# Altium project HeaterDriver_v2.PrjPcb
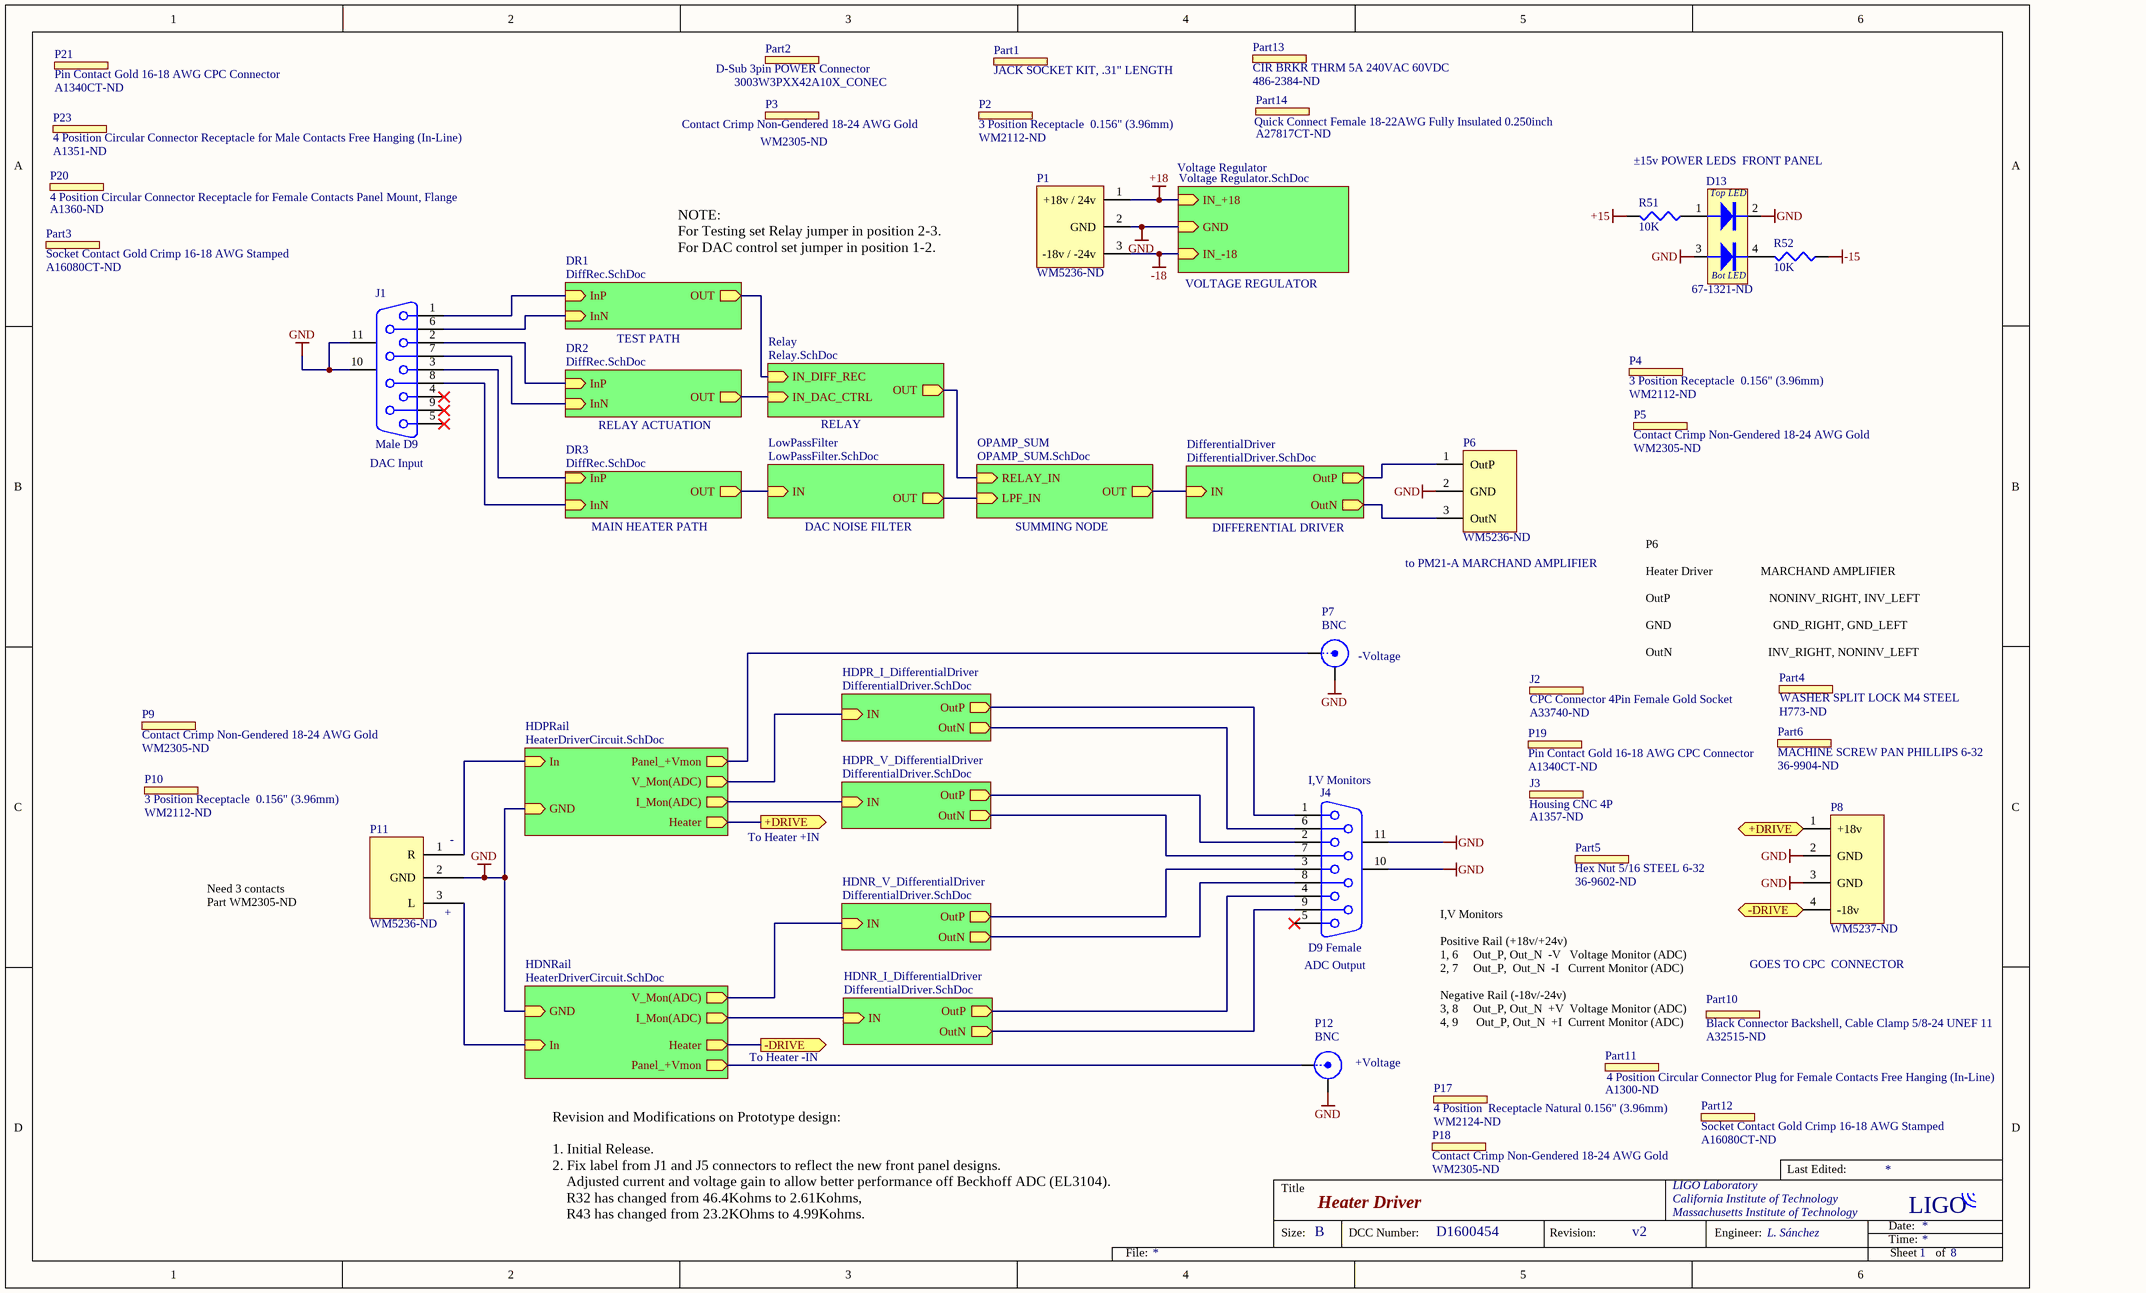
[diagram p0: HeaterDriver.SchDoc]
8 sheets, 310 parts. Net scope: hierarchical (ports join the sheet entries above them; power ports are global).
Board file: HeaterContollerDriver_v2.PcbDoc
Sheets:
  HeaterDriver.SchDoc
    Relay = Relay.SchDoc
    OPAMP_SUM = OPAMP_SUM.SchDoc
    LowPassFilter = LowPassFilter.SchDoc
    DR1 = DiffRec.SchDoc
    DR2 = DiffRec.SchDoc
    DR3 = DiffRec.SchDoc
    HDPR_I_DifferentialDriver = DifferentialDriver.SchDoc
    HDPR_V_DifferentialDriver = DifferentialDriver.SchDoc
    HDNR_I_DifferentialDriver = DifferentialDriver.SchDoc
    HDNR_V_DifferentialDriver = DifferentialDriver.SchDoc
    Voltage Regulator = Voltage Regulator.SchDoc
    HDPRail = HeaterDriverCircuit.SchDoc
    HDNRail = HeaterDriverCircuit.SchDoc
    DifferentialDriver = DifferentialDriver.SchDoc

## Sheet HeaterDriver.SchDoc: Heater Driver
size B; Organization: LIGO Laboratory; Address1: California Institute of Technology; Address2: Massachusetts Institute of Technology; DocumentNumber: D1600454; Revision: v2; SheetNumber: 1; SheetTotal: 8; Engineer: L. Sánchez

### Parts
D13  Digikey Part Number: 67-1321-ND  [my LUMEX Dual LED]  (hidden comment: Stacked LED)
J1  Male D9  [MY_DB9M_RA]
J2  CPC Connector 4Pin Female Gold Socket  Digikey Part Number: A33740-ND  (mechanical)
J3  Housing CNC 4P  Digikey Part Number: A1357-ND  (mechanical)
J4  D9 Female  [MY_DB9F_RA]
P1  Digikey Part Number: WM5236-ND  [MOLEX_156_3P_RA_PS_IN]  (hidden comment: Molex 3p 0.156inch RA)
P2  3 Position Receptacle  0.156" (3.96mm)  Digikey Part Number: WM2112-ND  (mechanical)
P3  Contact Crimp Non-Gendered 18-24 AWG Gold  Digikey Part Number: WM2305-ND  (mechanical)
P4  3 Position Receptacle  0.156" (3.96mm)  Digikey Part Number: WM2112-ND  (mechanical)
P5  Contact Crimp Non-Gendered 18-24 AWG Gold  Digikey Part Number: WM2305-ND  (mechanical)
P6  Digikey Part Number: WM5236-ND  [Header 0.156 3p PM21-A]  (hidden comment: Molex 3p 0.156inch RA)
P7  BNC  [BNC Straight Away Connector]
P8  Digikey Part Number: WM5237-ND  [HEADER  4p 0.156inch]  (hidden comment: Molex Header 4p 0.156inch RA)
P9  Contact Crimp Non-Gendered 18-24 AWG Gold  Digikey Part Number: WM2305-ND  (mechanical)
P10  3 Position Receptacle  0.156" (3.96mm)  Digikey Part Number: WM2112-ND  (mechanical)
P11  Digikey Part Number: WM5236-ND  [MOLEX_156_RA_3_+2Driver]  (hidden comment: Molex 3p 0.156inch RA)
P12  BNC  [BNC Straight Away Connector]
P17  4 Position  Receptacle Natural 0.156" (3.96mm)  Digikey Part Number: WM2124-ND  (mechanical)
P18  Contact Crimp Non-Gendered 18-24 AWG Gold  Digikey Part Number: WM2305-ND  (mechanical)
P19  Pin Contact Gold 16-18 AWG CPC Connector  Digikey Part Number: A1340CT-ND  (mechanical)
P20  4 Position Circular Connector Receptacle for Female Contacts Panel Mount, Flange  Digikey Part Number: A1360-ND  (mechanical)
P21  Pin Contact Gold 16-18 AWG CPC Connector  Digikey Part Number: A1340CT-ND  (mechanical)
P23  4 Position Circular Connector Receptacle for Male Contacts Free Hanging (In-Line)  Digikey Part Number: A1351-ND  (mechanical)
Part1  JACK SOCKET KIT, .31" LENGTH  (mechanical)
Part2  D-Sub 3pin POWER Connector  CONEC: 3003W3PXX42A10X_CONEC  (mechanical)
Part3  Socket Contact Gold Crimp 16-18 AWG Stamped  Digikey Part Number: A16080CT-ND  (mechanical)
Part4  WASHER SPLIT LOCK M4 STEEL  Digikey Part Number: H773-ND  (mechanical)
Part5  Hex Nut 5/16 STEEL 6-32  Digikey Part Number: 36-9602-ND  (mechanical)
Part6  MACHINE SCREW PAN PHILLIPS 6-32  Digikey Part Number: 36-9904-ND  (mechanical)
Part10  Black Connector Backshell, Cable Clamp 5/8-24 UNEF 11  Digikey Part Number: A32515-ND  (mechanical)
Part11  4 Position Circular Connector Plug for Female Contacts Free Hanging (In-Line)  Digikey Part Number: A1300-ND  (mechanical)
Part12  Socket Contact Gold Crimp 16-18 AWG Stamped  Digikey Part Number: A16080CT-ND  (mechanical)
Part13  CIR BRKR THRM 5A 240VAC 60VDC  Digikey Part Number: 486-2384-ND  (mechanical)
Part14  Quick Connect Female 18-22AWG Fully Insulated 0.250inch  Digikey Part Number: A27817CT-ND  (mechanical)
R51  value 10K  [1206]  (hidden comment: SMD Res 1206 10K 1% 0.25W)
R52  value 10K  [1206]  (hidden comment: SMD Res 1206 10K 1% 0.25W)

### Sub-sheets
DifferentialDriver = DifferentialDriver.SchDoc: IN (in), OutN (out), OutP (out)
DR1 = DiffRec.SchDoc: InP (in), InN (in), OUT (out)
DR2 = DiffRec.SchDoc: InP (in), InN (in), OUT (out)
DR3 = DiffRec.SchDoc: InP (in), InN (in), OUT (out)
HDNR_I_DifferentialDriver = DifferentialDriver.SchDoc: IN (in), OutN (out), OutP (out)
HDNR_V_DifferentialDriver = DifferentialDriver.SchDoc: IN (in), OutN (out), OutP (out)
HDNRail = HeaterDriverCircuit.SchDoc: In (in), GND (in), I_Mon(ADC) (out), Heater (out), Panel_+Vmon (out), V_Mon(ADC) (out)
HDPR_I_DifferentialDriver = DifferentialDriver.SchDoc: IN (in), OutN (out), OutP (out)
HDPR_V_DifferentialDriver = DifferentialDriver.SchDoc: IN (in), OutN (out), OutP (out)
HDPRail = HeaterDriverCircuit.SchDoc: In (in), GND (in), I_Mon(ADC) (out), Heater (out), Panel_+Vmon (out), V_Mon(ADC) (out)
LowPassFilter = LowPassFilter.SchDoc: IN (in), OUT (out)
OPAMP_SUM = OPAMP_SUM.SchDoc: RELAY_IN (in), LPF_IN (in), OUT (out)
Relay = Relay.SchDoc: IN_DAC_CTRL (in), IN_DIFF_REC (in), OUT (out)
Voltage Regulator = Voltage Regulator.SchDoc: IN_+18 (in), GND (in), IN_-18 (in)

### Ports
+DRIVE (out), -DRIVE (out)

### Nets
+15: R51.2
+18: P1.1(+18v_/_24v) ; sheet Voltage Regulator/IN_+18
-15: R52.1
-18: P1.3(-18v_/_-24v) ; sheet Voltage Regulator/IN_-18
GND: D13.2(CATHODE) D13.3(ANODE) J1.10(MH1) J1.11(MH2) J4.10(MH1) J4.11(MH2) P1.2(GND) P6.2(GND) P7.2(Y) P8.2(GND) P8.3(GND) P11.2(GND) P12.2(Y) ; sheet Voltage Regulator/GND, sheet HDPRail/GND, sheet HDNRail/GND
NetC5_1: sheet OPAMP_SUM/LPF_IN, sheet LowPassFilter/OUT
NetC19_HDNRail_2: sheet HDNR_V_DifferentialDriver/IN, sheet HDNRail/V_Mon(ADC)
NetC19_HDPRail_2: sheet HDPR_I_DifferentialDriver/IN, sheet HDPRail/V_Mon(ADC)
NetD13_1: D13.1(COM) R51.1
NetD13_4: D13.4(ANODE) R52.2
NetF3_HDNRail_1: P8.4(-18v) ; port -DRIVE, sheet HDNRail/Heater
NetF3_HDPRail_1: P8.1(+18v) ; port +DRIVE, sheet HDPRail/Heater
NetH1_1: sheet Relay/IN_DAC_CTRL, sheet DR2/OUT
NetJ1_1: J1.1 ; sheet DR1/InP
NetJ1_2: J1.2 ; sheet DR2/InP
NetJ1_3: J1.3 ; sheet DR3/InP
NetJ1_6: J1.6 ; sheet DR1/InN
NetJ1_7: J1.7 ; sheet DR2/InN
NetJ1_8: J1.8 ; sheet DR3/InN
NetJ4_1: J4.1 ; sheet HDPR_I_DifferentialDriver/OutP
NetJ4_2: J4.2 ; sheet HDPR_V_DifferentialDriver/OutP
NetJ4_3: J4.3 ; sheet HDNR_V_DifferentialDriver/OutP
NetJ4_4: J4.4 ; sheet HDNR_I_DifferentialDriver/OutP
NetJ4_6: J4.6 ; sheet HDPR_I_DifferentialDriver/OutN
NetJ4_7: J4.7 ; sheet HDPR_V_DifferentialDriver/OutN
NetJ4_8: J4.8 ; sheet HDNR_V_DifferentialDriver/OutN
NetJ4_9: J4.9 ; sheet HDNR_I_DifferentialDriver/OutN
NetP6_1: P6.1(OutP) ; sheet DifferentialDriver/OutP
NetP6_3: P6.3(OutN) ; sheet DifferentialDriver/OutN
NetP7_1: P7.1(X) ; sheet HDPRail/Panel_+Vmon
NetP11_1: P11.1(R) ; sheet HDPRail/In
NetP11_3: P11.3(L) ; sheet HDNRail/In
NetP12_1: P12.1(X) ; sheet HDNRail/Panel_+Vmon
NetR9_DR1_1: sheet Relay/IN_DIFF_REC, sheet DR1/OUT
NetR9_DR3_1: sheet LowPassFilter/IN, sheet DR3/OUT
NetR16_1: sheet Relay/OUT, sheet OPAMP_SUM/RELAY_IN
NetR23_2: sheet OPAMP_SUM/OUT, sheet DifferentialDriver/IN
NetR27_HDNR_I_DifferentialDriver_1: sheet HDNR_I_DifferentialDriver/IN, sheet HDNRail/I_Mon(ADC)
NetR27_HDPR_V_DifferentialDriver_1: sheet HDPR_V_DifferentialDriver/IN, sheet HDPRail/I_Mon(ADC)

Not connected (* = marked no-connect by the designer): J1 4* 5* 9*; J4 5*

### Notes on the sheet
- ±15v POWER LEDS  FRONT PANEL
- NOTE:
  For Testing set Relay jumper in position 2-3.
  For DAC control set jumper in position 1-2.
- VOLTAGE REGULATOR
- TEST PATH
- RELAY ACTUATION
- RELAY
- MAIN HEATER PATH
- DAC NOISE FILTER
- SUMMING NODE
- DIFFERENTIAL DRIVER
- (near P6) to PM21-A MARCHAND AMPLIFIER
- (near P7) -Voltage
- (near Part4) P6
  Heater Driver                MARCHAND AMPLIFIER
  OutP                                 NONINV_RIGHT, INV_LEFT
  GND                                  GND_RIGHT, GND_LEFT
  OutN                                INV_RIGHT, NONINV_LEFT
- To Heater +IN
- Need 3 contacts
  Part WM2305-ND
- GOES TO CPC  CONNECTOR
- I,V Monitors
  Positive Rail (+18v/+24v)
  1, 6     Out_P, Out_N  -V   Voltage Monitor (ADC)
  2, 7     Out_P,  Out_N  -I   Current Monitor (ADC)
  Negative Rail (-18v/-24v)
  3, 8     Out_P, Out_N  +V  Voltage Monitor (ADC)
  4, 9      Out_P, Out_N  +I  Current Monitor (ADC)
- To Heater -IN
- (near P12) +Voltage
- Revision and Modifications on Prototype design:
  1. Initial Release.
  2. Fix label from J1 and J5 connectors to reflect the new front panel designs.
  Adjusted current and voltage gain to allow better performance off Beckhoff ADC (EL3104).
  R32 has changed from 46.4Kohms to 2.61Kohms,
  R43 has changed from 23.2KOhms to 4.99Kohms.

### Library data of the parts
D13 = Dual Stacked LED: Dual Green LED; Manufacturers Part Number: SSF-LXH240GGD; Checked: yes; Value: 67-1321-ND
J1 = D Connector 9: Receptacle Assembly, 9 Position, Right Angle; Manufacturers Part Number: 6E17C-009P-AJ-121; Checked: y; Value: 6E17C-009P-AJ-121-ND
J2 = Mechanical Part: Manufacturers Part Number: 208283-4; Checked: y; Value: A33740-ND
J3 = Mechanical Part: Manufacturers Part Number: 206429-1; Checked: yes; Value: A1357-ND
J4 = D Connector 9: Receptacle Assembly, 9 Position, Right Angle; Manufacturers Part Number: 5747844-4; Checked: y; Value: A32117-ND
P1 = Header 3p 156 IN: Manufacturers Part Number: 0026615030; Checked: yes; Value: WM5236-ND
P2 P4 = Mechanical Part: Manufacturers Part Number: 0009508033; Checked: Yes; Value: WM2112-ND
P3 P5 P18 = Mechanical Part: Manufacturers Part Number: 0008560106; Checked: Yes; Value: WM2305-ND
P6 = Header 3p 156 Out Marchand: Manufacturers Part Number: 0026615030; Checked: yes; Value: WM5236-ND
P7 P12 = BNC: BNC Straight Away Connector; Manufacturers Part Number: 5227161-7; Checked: y; Value: A32260-ND
P8 = Header 4p 0.156inch: Manufacturers Part Number: 0026615040; Checked: yes
P9 = Mechanical Part: Manufacturers Part Number: 0008560106; Checked: yes; Value: WM2305-ND
P10 = Mechanical Part: 3 Position Rectangular Housing Connector Receptacle Natural 0.156" (3.96mm); Manufacturers Part Number: 0009508033; Checked: yes; Value: WM2112-ND
P11 = Header 3p 156 +2Driver: Manufacturers Part Number: 0026615030; Checked: yes
P17 = Mechanical Part: Manufacturers Part Number: 0009508041; Checked: yes
P19 P21 = Mechanical Part: Manufacturers Part Number: 66098-9; Checked: yes; Value: A1340CT-ND
P20 = Mechanical Part: Manufacturers Part Number: 206430-1; Checked: Yes
P23 = Mechanical Part: Manufacturers Part Number: 206153-1; Checked: yes
Part1 = Mechanical Part: Manufacturers Part Number: 3341-1S; Checked: yes; Value: 523-17-D20418-2-TX
Part2 = Mechanical Part: CONEC: 3003W3PXX42A10X; Checked: yes; Value: 3003W3PXX42A10X
Part3 Part12 = Mechanical Part: Manufacturers Part Number: 66100-9; Checked: yes
Part4 = Mechanical Part: Manufacturers Part Number: MLWZ 004; Checked: yes; Value: H773-ND
Part5 = Mechanical Part: Checked: yes; Value: 9602
Part6 = Mechanical Part: Checked: yes; Value: 9904
Part10 = Mechanical Part: Manufacturers Part Number: 1-206062-4; Checked: yes
Part11 = Mechanical Part: Manufacturers Part Number: 206060-1; Checked: yes
Part13 = Mechanical Part: Manufacturers Part Number: 4435.0039; Checked: yes
Part14 = Mechanical Part: Manufacturers Part Number: 2-520183-2; Checked: yes
R51 R52 = 1206_Res_10K 1%: Manufacturers Part Number: RNCP1206FTD10K0; Checked: yes

## Sheet Relay.SchDoc: Relay
size A; Organization: LIGO Laboratory; Address1: California Institute of Technology; Address2: Massachusetts Institute of Technology; DocumentNumber: D1600454; Revision: v1; SheetNumber: 3; SheetTotal: 8; Engineer: L.Sánchez
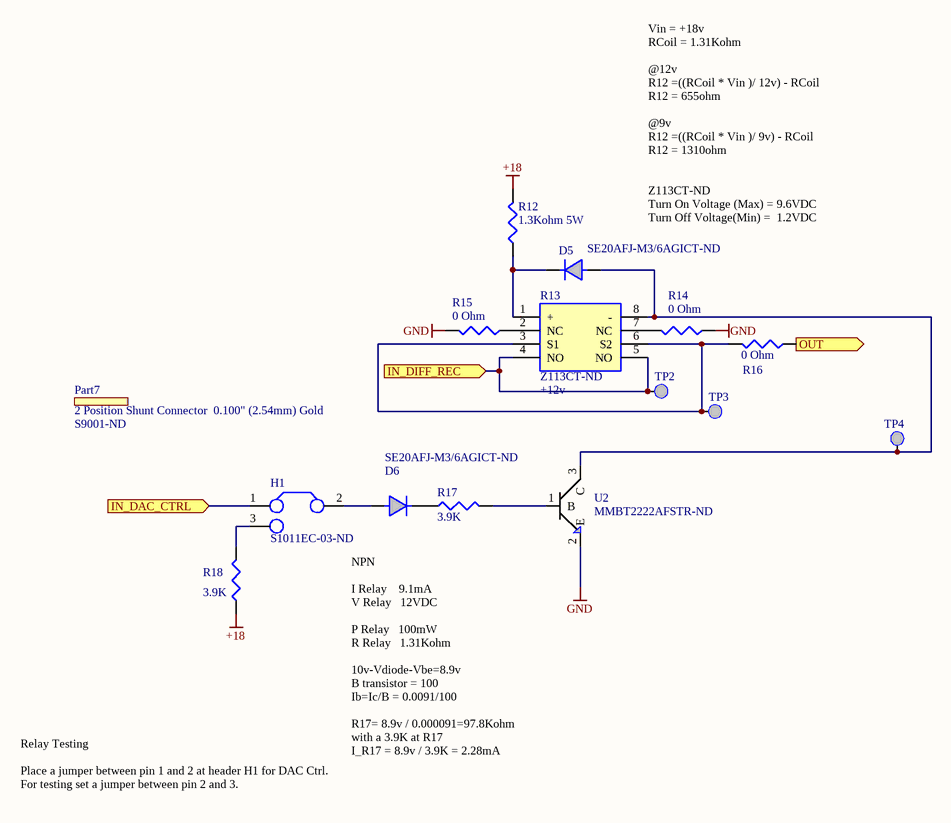
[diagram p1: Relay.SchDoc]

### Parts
D5  Supplier Part Number 1: SE20AFJ-M3/6AGICT-ND  [DIODE_SE20AFJ-M3/6A]  (hidden comment: Diode General)
D6  Supplier Part Number 1: SE20AFJ-M3/6AGICT-ND  [DIODE_SE20AFJ-M3/6A]  (hidden comment: Diode General)
H1  Digikey Part Number: S1011EC-03-ND  [Jumper 3P]  (hidden comment: Header 3P Gold Unshrouded 0.100inch)
Part7  2 Position Shunt Connector  0.100" (2.54mm) Gold  Digikey Part Number: S9001-ND  (mechanical)
R12  value 1.3Kohm 5W  [Axial_Res_925]  (hidden comment: Res 1.3Kohm, 5W,5% Axial)
R13  Supplier Part Number 1: Z113CT-ND  [RELAY_G6K-2F-TR-DC5]  (hidden comment: Relay DPDT SMD 12v DC)
R14  0 Ohm  [3216[1206]]
R15  0 Ohm  [3216[1206]]
R16  0 Ohm  [3216[1206]]
R17  value 3.9K  [1206]  (hidden comment: SMD Res 3.9K 0.1% 0.25W 1206)
R18  value 3.9K  [1206]  (hidden comment: SMD Res 3.9K 0.1% 0.25W 1206)
TP2  TESTPT  [smt_tp]  (value not drawn)
TP3  TESTPT  [smt_tp]  (value not drawn)
TP4  TESTPT  [smt_tp]  (value not drawn)
U2  Supplier Part Number 1: MMBT2222AFSTR-ND  [SOT-23-3]  (hidden comment: Transistor Switch NPN General Purpose 40v 1Amp)

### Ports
IN_DAC_CTRL (in), IN_DIFF_REC (in), OUT (out)

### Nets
+18: R12.2 R18.1
GND: R14.1 R15.2 U2.2(E)
NetD5_1: D5.1(K) R12.1 R13.1(+)
NetD5_2: D5.2(A) R13.8(-) TP4.1 U2.3(C)
NetD6_1: D6.1(K) R17.1
NetD6_2: D6.2(A) H1.2
NetH1_1: H1.1 ; port IN_DAC_CTRL
NetH1_3: H1.3 R18.2
NetR9_DR1_1: R13.4(NO) R13.5(NO) TP2.1 ; port IN_DIFF_REC
NetR13_2: R13.2(NC) R15.1
NetR13_3: R13.3(S1) R13.6(S2) R16.2 TP3.1
NetR13_7: R13.7(NC) R14.2
NetR16_1: R16.1 ; port OUT
NetR17_2: R17.2 U2.1(B)

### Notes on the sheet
- Vin = +18v
  RCoil = 1.31Kohm
  @12v
  R12 =((RCoil * Vin )/ 12v) - RCoil
  R12 = 655ohm
  @9v
  R12 =((RCoil * Vin )/ 9v) - RCoil
  R12 = 1310ohm
  Z113CT-ND
  Turn On Voltage (Max) = 9.6VDC
  Turn Off Voltage(Min) =  1.2VDC
- NPN
  I Relay    9.1mA
  V Relay   12VDC
  P Relay   100mW
  R Relay   1.31Kohm
  10v-Vdiode-Vbe=8.9v
  B transistor = 100
  Ib=Ic/B = 0.0091/100
  R17= 8.9v / 0.000091=97.8Kohm
  with a 3.9K at R17
  I_R17 = 8.9v / 3.9K = 2.28mA
- Relay Testing
  Place a jumper between pin 1 and 2 at header H1 for DAC Ctrl.
  For testing set a jumper between pin 2 and 3.

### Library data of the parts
D5 D6 = DIODE_SE20AFJ-M3/6A: Checked: y; Value: SE20AFJ-M3/6AGICT-ND
H1 = Header_3P: Manufacturers Part Number: PRPC003SAAN-RC; Checked: Yes; Value: S1011EC-03-ND
Part7 = Mechanical Part: 2 (1 x 2) Position Shunt Connector Black Closed Top 0.100" (2.54mm) Gold; Manufacturers Part Number: SPC02SYAN; Checked: yes; Value: S9001-ND
R12 = Axial_TH_Res_1.30K_5W: Manufacturers Part Number: SQP500JB-1K3; Checked: yes
R13 = RELAY_G6K-2F-TR-DC12
R14-R16 = Res3: Resistor; 'Manufacturers Part Number: ERJ-8GEY0R00V; Checked: y
R17 R18 = 1206_Res_3.9K: Manufacturers Part Number: ERA-8AEB392V; Checked: yes
TP2-TP4 = TESTPT: PCB Testpoint; 'Manufacturers Part Number: 5016; Checked: Yes; Value: 36-5016CT-ND
U2 = MMBT2222A_NPN: Checked: yes; Value: MMBT2222AFSTR-ND

## Sheet OPAMP_SUM.SchDoc: OP AMP SUM
size A; Organization: LIGO Laboratory; Address1: California Institute of Technology; Address2: Massachusetts Institute of Technology; DocumentNumber: D1600454; Revision: v2; SheetNumber: 5; SheetTotal: 8; Engineer: L.Sánchez
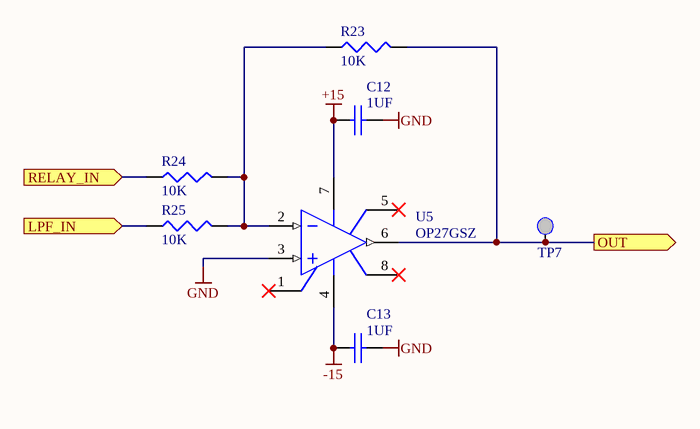
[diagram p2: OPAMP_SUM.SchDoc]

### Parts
C12  1UF  [3216[1206]]
C13  1UF  [3216[1206]]
R23  value 10K  [1206]  (hidden comment: 10K Resistor 1206 0.25W 0.1%)
R24  value 10K  [1206]  (hidden comment: 10K Resistor 1206 0.25W 0.1%)
R25  value 10K  [1206]  (hidden comment: 10K Resistor 1206 0.25W 0.1%)
TP7  TESTPT  [smt_tp]  (value not drawn)
U5  OP27GSZ  [SO8_N]

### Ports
LPF_IN (in), OUT (out), RELAY_IN (in)

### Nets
+15: C12.1 U5.7(V+)
-15: C13.1 U5.4(V-)
GND: C12.2 C13.2 U5.3(IN+)
NetC5_1: R25.1 ; port LPF_IN
NetR16_1: R24.1 ; port RELAY_IN
NetR23_1: R23.1 R24.2 R25.2 U5.2(IN-)
NetR23_2: R23.2 TP7.1 U5.6(OUT) ; port OUT

Not connected (* = marked no-connect by the designer): U5 1(NULL1)* 5(NC)* 8(NULL2)*

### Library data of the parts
C12 C13 = MYCAP: CAP 1.0UF 50V CERAMIC F 1206; Manufacturers Part Number: 12065G105ZAT2A; Checked: y
R23-R25 = 1206_Res_10K: SMD 1206 Resistor 10K 0.25W 0.1%; Manufacturers Part Number: ERA-8AEB103V; Checked: yes
TP7 = TESTPT: as TP2 on sheet Relay
U5 = ADOP27AQ: Ultra-Low Noise, Precision Operational Amplifier; Checked: y; Value: OP27GSZ-ND

## Sheet LowPassFilter.SchDoc: Low Pass Filter
size A; Organization: LIGO Laboratory; Address1: California Institute of Technology; Address2: Massachusetts Institute of Technology; DocumentNumber: D1600454; Revision: v2; SheetNumber: 4; SheetTotal: 8; Engineer: L.Sánchez
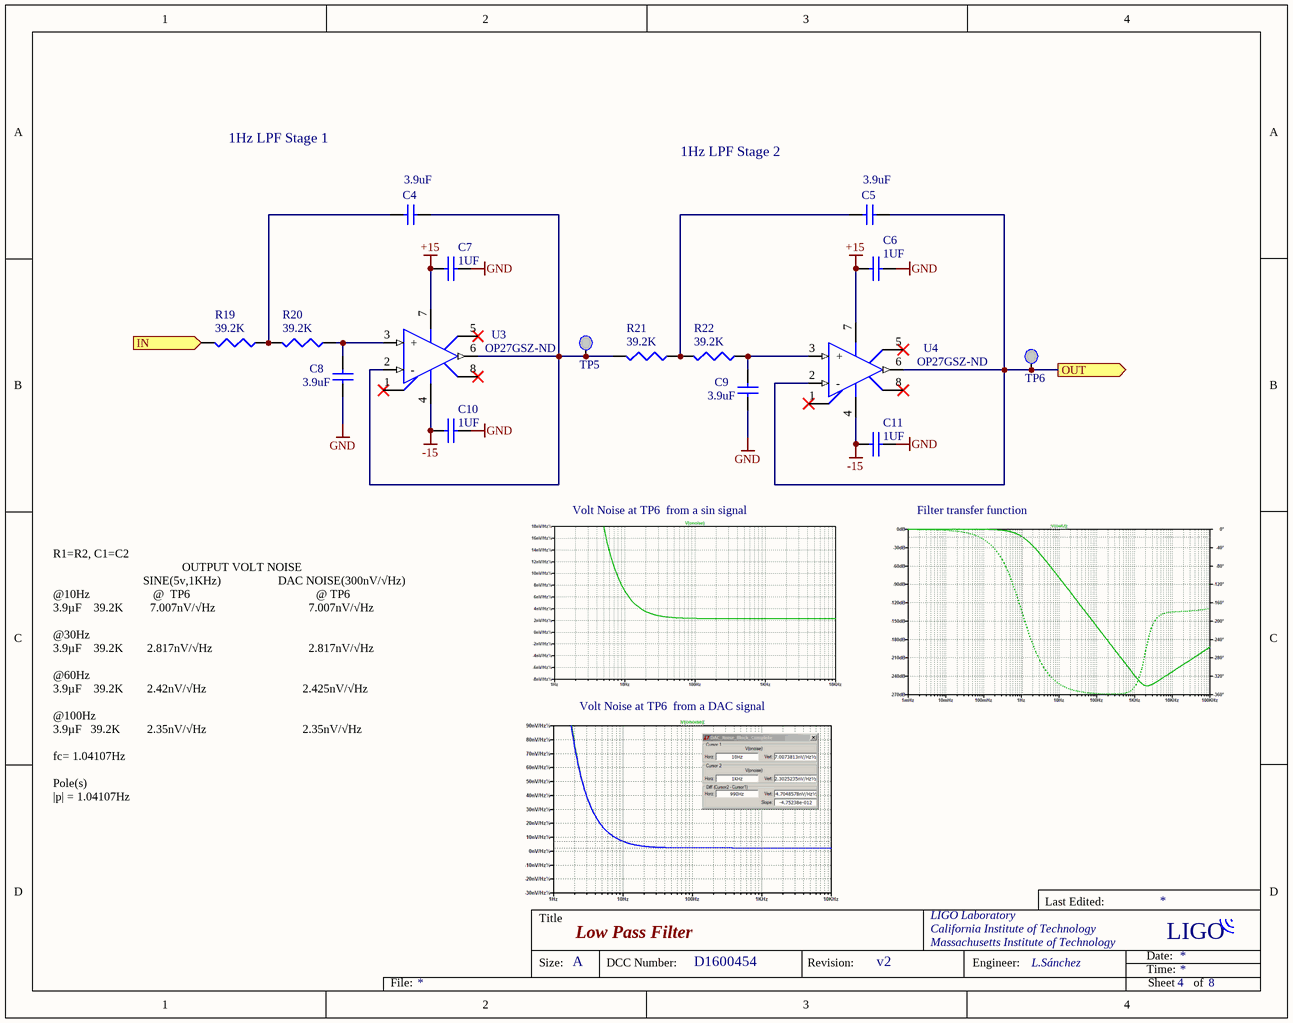
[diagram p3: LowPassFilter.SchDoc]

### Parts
C4  value 3.9uF  [CAP_FILM_0.689inch]  (hidden comment: Cap Film 3.9uF 250v 10%)
C5  value 3.9uF  [CAP_FILM_0.689inch]  (hidden comment: Cap Film 3.9uF 250v 10%)
C6  1UF  [3216[1206]]
C7  1UF  [3216[1206]]
C8  value 3.9uF  [CAP_FILM_0.689inch]  (hidden comment: Cap Film 3.9uF 250v 10%)
C9  value 3.9uF  [CAP_FILM_0.689inch]  (hidden comment: Cap Film 3.9uF 250v 10%)
C10  1UF  [3216[1206]]
C11  1UF  [3216[1206]]
R19  39.2K  [3216[1206]]
R20  39.2K  [3216[1206]]
R21  39.2K  [3216[1206]]
R22  39.2K  [3216[1206]]
TP5  TESTPT  [smt_tp]  (value not drawn)
TP6  TESTPT  [smt_tp]  (value not drawn)
U3  Digikey Part Number: OP27GSZ-ND  [SOIC_8P_]  (hidden comment: OP27GSZ)
U4  Digikey Part Number: OP27GSZ-ND  [SOIC_8P_]  (hidden comment: OP27GSZ)

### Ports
IN (in), OUT (out)

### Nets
+15: C6.1 C7.1 U3.7(v+) U4.7(v+)
-15: C10.1 C11.1 U3.4(v-) U4.4(v-)
GND: C6.2 C7.2 C8.1 C9.1 C10.2 C11.2
NetC4_1: C4.1 R21.2 TP5.1 U3.2(-) U3.6(out)
NetC4_2: C4.2 R19.1 R20.2
NetC5_1: C5.1 TP6.1 U4.2(-) U4.6(out) ; port OUT
NetC5_2: C5.2 R21.1 R22.2
NetC8_2: C8.2 R20.1 U3.3(+)
NetC9_2: C9.2 R22.1 U4.3(+)
NetR9_DR3_1: R19.2 ; port IN

Not connected (* = marked no-connect by the designer): U3 1* 5* 8*; U4 1* 5* 8*

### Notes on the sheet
- 1Hz LPF Stage 1
- 1Hz LPF Stage 2
- Volt Noise at TP6  from a sin signal
- Filter transfer function
- Volt Noise at TP6  from a DAC signal
- R1=R2, C1=C2
  OUTPUT VOLT NOISE
  SINE(5v,1KHz)                   DAC NOISE(300nV/√Hz)
  @10Hz                     @  TP6                                          @ TP6
  3.9µF    39.2K         7.007nV/√Hz                               7.007nV/√Hz
  @30Hz
  3.9µF    39.2K        2.817nV/√Hz                                2.817nV/√Hz
  @60Hz
  3.9µF    39.2K        2.42nV/√Hz                                2.425nV/√Hz
  @100Hz
  3.9µF   39.2K         2.35nV/√Hz                                2.35nV/√Hz
  fc= 1.04107Hz
  Pole(s)
  |p| = 1.04107Hz

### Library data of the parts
C4 C5 C8 C9 = CAP_Radial_3.9uF_250v: Manufacturers Part Number: ECQ-E2395KB; Checked: y
C6 C7 C10 C11 = MYCAP: as C12 on sheet OPAMP_SUM
R19-R22 = MYRES: 39.2K Film Resistor; 'Manufacturers Part Number: ERA-8AEB3922V; Checked: y
TP5 TP6 = TESTPT: as TP2 on sheet Relay
U3 U4 = OP27_Low Noise Precision OPAMP: Ultra-Low Noise, Precision Operational Amplifier; Checked: yes

## Sheet DiffRec.SchDoc: Differential Receiver
size A; Organization: LIGO Laboratory; Address1: California Institute of Technology; Address2: Massachusetts Institute of Technology; DocumentNumber: D1600454; Revision: v2; SheetNumber: 2; SheetTotal: 8; Engineer: L.Sanchez
Used 3 times, as channels DR1, DR2, DR3. Parts and nets are listed once, with the designators drawn on the sheet.
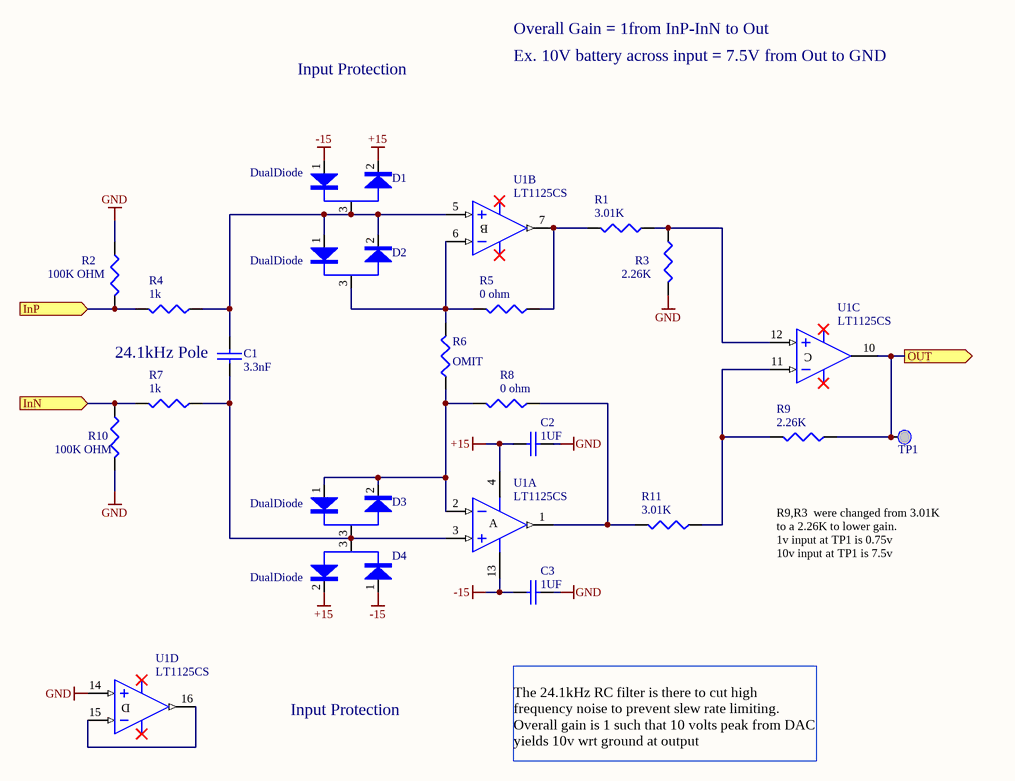
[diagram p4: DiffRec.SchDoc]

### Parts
C1  3.3nF  [3216[1206]]
C2  1UF  [3216[1206]]
C3  1UF  [3216[1206]]
D1  DualDiode  [SOT-23A]
D2  DualDiode  [SOT-23A]
D3  DualDiode  [SOT-23A]
D4  DualDiode  [SOT-23A]
R1  3.01K  [3216[1206]]
R2  100K OHM  [3216[1206]]
R3  value 2.26K  [3216[1206]]  (hidden comment: RES SMD 2.26K OHM 0.1% 1/4W 1206)
R4  1k  [3216[1206]]
R5  0 ohm  [3216[1206]]
R6  OMIT  [3216[1206]]
R7  1k  [3216[1206]]
R8  0 ohm  [3216[1206]]
R9  value 2.26K  [3216[1206]]  (hidden comment: RES SMD 2.26K OHM 0.1% 1/4W 1206)
R10  100K OHM  [3216[1206]]
R11  3.01K  [3216[1206]]
TP1  TESTPT  [smt_tp]  (value not drawn)
U1  LT1125CS  [SOIC127P1030-16N]  (parts A,B,C,D of 4)

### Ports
InN (in), InP (in), OUT (out)

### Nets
+15: C2.1 D1.2(CATHODE) D4.2(CATHODE) U1.4(V+)
-15: C3.1 D1.1(ANODE) D4.1(ANODE) U1.13(V-)
GND: C2.2 C3.2 R2.1 R3.2 R10.2 U1.14(IN+)
InN: R7.2 R10.1 ; port InN
InP: R2.2 R4.2 ; port InP
OUT: R9.1 TP1.1 U1.10(OUT) ; port OUT
NetC1_1: C1.1 D3.3(COM) D4.3(COM) R7.1 U1.3(IN+)
NetC1_2: C1.2 D1.3(COM) D2.1(ANODE) D2.2(CATHODE) R4.1 U1.5(IN+)
NetD2_3: D2.3(COM) R5.2 R6.2 U1.6(IN-)
NetD3_1: D3.1(ANODE) D3.2(CATHODE) R6.1 R8.2 U1.2(IN-)
NetR1_1: R1.1 R3.1 U1.12(IN+)
NetR1_2: R1.2 R5.1 U1.7(OUT)
NetR8_1: R8.1 R11.2 U1.1(OUT)
NetR9_2: R9.2 R11.1 U1.11(IN-)
NetU1_15: U1.15(IN-) U1.16(OUT)

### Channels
DR1: designators end in _DR1; ports InN=NetJ1_6 InP=NetJ1_1 OUT=NetR9_DR1_1
DR2: designators end in _DR2; ports InN=NetJ1_7 InP=NetJ1_2 OUT=NetH1_1
DR3: designators end in _DR3; ports InN=NetJ1_8 InP=NetJ1_3 OUT=NetR9_DR3_1

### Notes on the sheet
- Overall Gain = 1from InP-InN to Out
- Input Protection
- Ex. 10V battery across input = 7.5V from Out to GND
- (near C1) 24.1kHz Pole
- R9,R3  were changed from 3.01K to a 2.26K to lower gain.
  1v input at TP1 is 0.75v
  10v input at TP1 is 7.5v
- The 24.1kHz RC filter is there to cut high frequency noise to prevent slew rate limiting. Overall gain is 1 such that 10 volts peak from DAC yields 10v wrt ground at output

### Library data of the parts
C1 = MYCAP: CAP 3.3nF 50V PPS 1206; Manufacturers Part Number: ECH-U1H332GX5; checked: y
C2 C3 = MYCAP: CAP 1.0UF 50V CERAMIC F 1206; Manufacturers Part Number: 12065G105ZAT2A; checked: y
D1-D4 = DualDiode: DUAL SERIES DIODE.; Manufacturers Part Number: BAS70-04LT1G; Checked: y; Value: BAS70-04LT1GOSCT-ND
R1 R11 = MYRES: Resistor; 'Manufacturers Part Number: ERA-8AEB3011V; checked: y
R2 R10 = MYRES: Resistor; 'Manufacturers Part Number: ERA-8AEB104V; checked: y
R3 R9 = MYRES: 'Manufacturers Part Number: ERA-8AEB3011V; Manufacturers Part Number: ERA-8AEB2261V; checked: y
R4 R7 = MYRES: Resistor; 'Manufacturers Part Number: ERA-8AEB102V; checked: y
R5 R8 = MYRES: Resistor; 'Manufacturers Part Number: ERJ-8GEY0R00V; checked: y
R6 = MYRES: Resistor; checked: y
TP1 = TESTPT: as TP2 on sheet Relay
U1 = LT1125CS: Quad Low Noise, High-Speed Precision Operational Amplifier; 'Manufacturers Part Number: LT1125CSW#PBF; checked: y

## Sheet DifferentialDriver.SchDoc: Differential Driver
size A; Organization: LIGO Laboratory; Address1: California Institute of Technology; Address2: Massachusetts Institute of Technology; DocumentNumber: D1600454; Revision: v2; SheetNumber: 6; SheetTotal: 8; Engineer: L.Sanchez
Used 5 times, as channels HDPR_I_DifferentialDriver, HDPR_V_DifferentialDriver, HDNR_I_DifferentialDriver, HDNR_V_DifferentialDriver, DifferentialDriver. Parts and nets are listed once, with the designators drawn on the sheet.
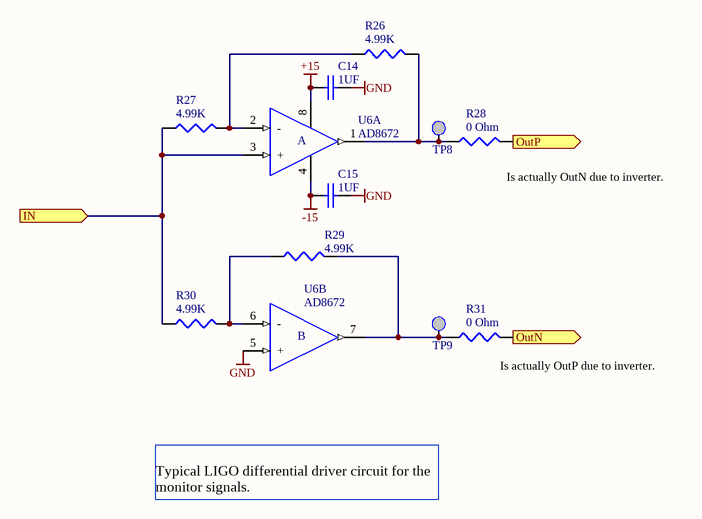
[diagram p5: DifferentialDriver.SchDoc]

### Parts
C14  1UF  [3216[1206]]
C15  1UF  [3216[1206]]
R26  4.99K  [3216[1206]]
R27  4.99K  [3216[1206]]
R28  0 Ohm  [3216[1206]]
R29  4.99K  [3216[1206]]
R30  4.99K  [3216[1206]]
R31  0 Ohm  [3216[1206]]
TP8  TESTPT  [smt_tp]  (value not drawn)
TP9  TESTPT  [smt_tp]  (value not drawn)
U6  AD8672  [SOIC_8P_]  (parts A,B of 2)

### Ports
IN (in), OutN (out), OutP (out)

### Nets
+15: C14.2 U6.8
-15: C15.2 U6.4
GND: C14.1 C15.1 U6.5(+)
IN: R27.1 R30.1 U6.3(+) ; port IN
OutN: R31.2 ; port OutN
OutP: R28.2 ; port OutP
NetR26_1: R26.1 R27.2 U6.2(-)
NetR26_2: R26.2 R28.1 TP8.1 U6.1
NetR29_1: R29.1 R30.2 U6.6(-)
NetR29_2: R29.2 R31.1 TP9.1 U6.7

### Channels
HDPR_I_DifferentialDriver: designators end in _HDPR_I_DifferentialDriver; ports IN=NetC19_HDPRail_2 OutN=NetJ4_6 OutP=NetJ4_1
HDPR_V_DifferentialDriver: designators end in _HDPR_V_DifferentialDriver; ports IN=NetR27_HDPR_V_DifferentialDriver_1 OutN=NetJ4_7 OutP=NetJ4_2
HDNR_I_DifferentialDriver: designators end in _HDNR_I_DifferentialDriver; ports IN=NetR27_HDNR_I_DifferentialDriver_1 OutN=NetJ4_9 OutP=NetJ4_4
HDNR_V_DifferentialDriver: designators end in _HDNR_V_DifferentialDriver; ports IN=NetC19_HDNRail_2 OutN=NetJ4_8 OutP=NetJ4_3
DifferentialDriver: designators end in _DifferentialDriver; ports IN=NetR23_2 OutN=NetP6_3 OutP=NetP6_1

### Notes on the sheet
- (near R28) Is actually OutN due to inverter.
- (near R31) Is actually OutP due to inverter.
- Typical LIGO differential driver circuit for the monitor signals.

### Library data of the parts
C14 C15 = MYCAP: as C12 on sheet OPAMP_SUM
R26 R27 R29 R30 = Res3: Resistor; 'Manufacturers Part Number: TNPW12064K99BEEA; Checked: y
R28 R31 = Res3: as R14 on sheet Relay
TP8 TP9 = TESTPT: as TP2 on sheet Relay
U6 = AD8672: High-Speed, Low-Power Dual Operational Amplifier; 'Manufacturers Part Number: AD8672ARZ-REEL7; Checked: Yes

## Sheet Voltage Regulator.SchDoc: Voltage Regulator
size A; Organization: LIGO Laboratory; Address1: California Institute of Technology; Address2: Massachusetts Institute of Technology; DocumentNumber: D1600454; Revision: v2; SheetNumber: 8; SheetTotal: 8; Engineer: L.Sánchez
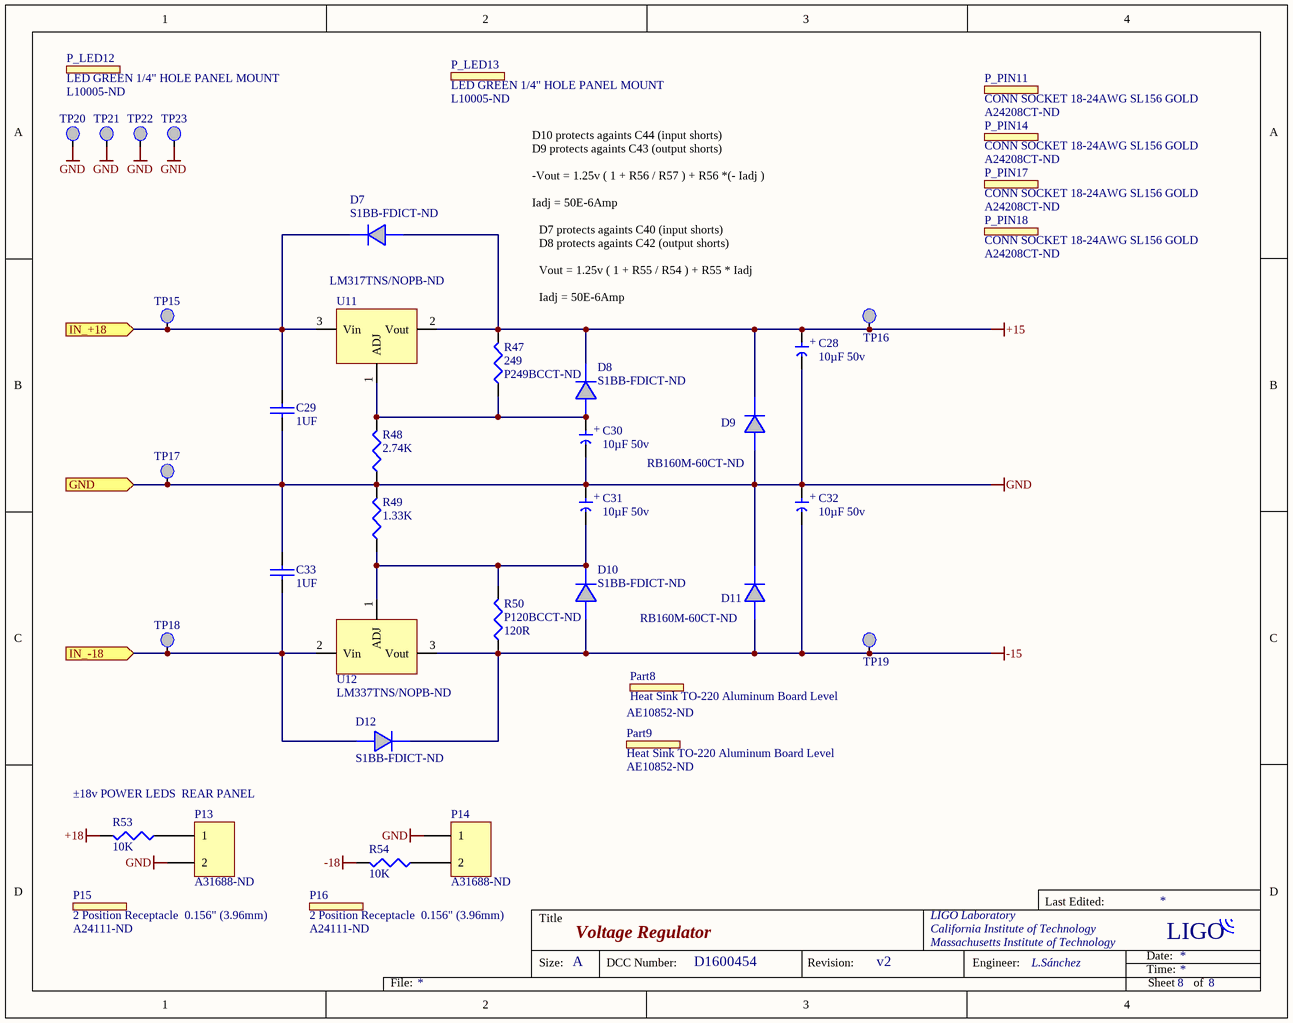
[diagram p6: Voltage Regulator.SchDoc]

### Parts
C28  value 10µF 50v  [2916]  (hidden comment: SMD Cap Tantalum Poly 10uF 50v 2917)
C29  1UF  [3216[1206]]
C30  value 10µF 50v  [2916]  (hidden comment: SMD Cap Tantalum Poly 10uF 50v 2917)
C31  value 10µF 50v  [2916]  (hidden comment: SMD Cap Tantalum Poly 10uF 50v 2917)
C32  value 10µF 50v  [2916]  (hidden comment: SMD Cap Tantalum Poly 10uF 50v 2917)
C33  1UF  [3216[1206]]
D7  Supplier Part Number 1: S1BB-FDICT-ND  [DIODE_SMB]  (hidden comment: Diode Standard 100V 1A Surface Mount SMB)
D8  Supplier Part Number 1: S1BB-FDICT-ND  [DIODE_SMB]  (hidden comment: Diode Standard 100V 1A Surface Mount SMB)
D9  Supplier Part Number 1: RB160M-60CT-ND  [SOD-123F]  (hidden comment: Diode Schottky 60v 1A SMT PMDU SOD-123F)
D10  Supplier Part Number 1: S1BB-FDICT-ND  [DIODE_SMB]  (hidden comment: Diode Standard 100V 1A Surface Mount SMB)
D11  Supplier Part Number 1: RB160M-60CT-ND  [SOD-123F]  (hidden comment: Diode Schottky 60v 1A SMT PMDU SOD-123F)
D12  Supplier Part Number 1: S1BB-FDICT-ND  [DIODE_SMB]  (hidden comment: Diode Standard 100V 1A Surface Mount SMB)
P13  Digikey Part Number: A31688-ND  [MOLEX_156_2]  (hidden comment: Header 2P 0.156inch RA)
P14  Digikey Part Number: A31688-ND  [MOLEX_156_2]  (hidden comment: Header 2P 0.156inch RA)
P15  2 Position Receptacle  0.156" (3.96mm)  Digikey Part Number: A24111-ND  (mechanical)
P16  2 Position Receptacle  0.156" (3.96mm)  Digikey Part Number: A24111-ND  (mechanical)
P_LED12  LED GREEN 1/4" HOLE PANEL MOUNT  Digikey Part Number: L10005-ND  (mechanical)
P_LED13  LED GREEN 1/4" HOLE PANEL MOUNT  Digikey Part Number: L10005-ND  (mechanical)
P_PIN11  CONN SOCKET 18-24AWG SL156 GOLD  Digikey Part Number: A24208CT-ND  (mechanical)
P_PIN14  CONN SOCKET 18-24AWG SL156 GOLD  Digikey Part Number: A24208CT-ND  (mechanical)
P_PIN17  CONN SOCKET 18-24AWG SL156 GOLD  Digikey Part Number: A24208CT-ND  (mechanical)
P_PIN18  CONN SOCKET 18-24AWG SL156 GOLD  Digikey Part Number: A24208CT-ND  (mechanical)
Part8  Heat Sink TO-220 Aluminum Board Level  Digikey Part Number: AE10852-ND  (mechanical)
Part9  Heat Sink TO-220 Aluminum Board Level  Digikey Part Number: AE10852-ND  (mechanical)
R47  value 249  Supplier Part Number 1: P249BCCT-ND  [1206]  (hidden comment: SMD Res 249Ohm 0.1% 0.25W 1206)
R48  value 2.74K  [1206]  (hidden comment: SMD Res 2.74K 0.1%  0.25W 1206)
R49  value 1.33K  [1206]  (hidden comment: SMD Res 1.33K 0.1% 0.25W 1206)
R50  value 120R  Supplier Part Number 1: P120BCCT-ND  [1206]  (hidden comment: SMD Res 120ohm 0.1% 0.25W  1206)
R53  value 10K  [1206]  (hidden comment: SMD Res 1206 10K 1% 0.25W)
R54  value 10K  [1206]  (hidden comment: SMD Res 1206 10K 1% 0.25W)
TP15  TESTPT  [smt_tp]  (value not drawn)
TP16  TESTPT  [smt_tp]  (value not drawn)
TP17  TESTPT  [smt_tp]  (value not drawn)
TP18  TESTPT  [smt_tp]  (value not drawn)
TP19  TESTPT  [smt_tp]  (value not drawn)
TP20  TESTPT  [smt_tp]  (value not drawn)
TP21  TESTPT  [smt_tp]  (value not drawn)
TP22  TESTPT  [smt_tp]  (value not drawn)
TP23  TESTPT  [smt_tp]  (value not drawn)
U11  Supplier Part Number 1: LM317TNS/NOPB-ND  [MY_TO220_HeatSink]  (hidden comment: Linear Voltage Reg + 1.25v to 37v 1.5A TO-220-3)
U12  Supplier Part Number 1: LM337TNS/NOPB-ND  [MY_TO220_HeatSink]  (hidden comment: Linear Voltage Reg -1.2v to -37v  1.5A TO-220-3)

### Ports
GND (in), IN_+18 (in), IN_-18 (in)

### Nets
+15: C28.1 D7.2(A) D8.1(K) D9.1(A) R47.2 TP16.1 U11.2(Vout)
+18: C29.2 D7.1(K) R53.2 TP15.1 U11.3(Vin) ; port IN_+18
-15: C32.2 D10.2(A) D11.2(K) D12.1(K) R50.1 TP19.1 U12.3(Vout)
-18: C33.1 D12.2(A) R54.2 TP18.1 U12.2(Vin) ; port IN_-18
GND: C28.2 C29.1 C30.2 C31.1 C32.1 C33.2 D9.2(K) D11.1(A) P13.2 P14.1 R48.1 R49.2 TP17.1 TP20.1 TP21.1 TP22.1 TP23.1 ; port GND
NetC30_1: C30.1 D8.2(A) R47.1 R48.2 U11.1(ADJ)
NetC31_2: C31.2 D10.1(K) R49.1 R50.2 U12.1(ADJ)
NetP13_1: P13.1 R53.1
NetP14_2: P14.2 R54.1

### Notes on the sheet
- D10 protects againts C44 (input shorts)
  D9 protects againts C43 (output shorts)
  -Vout = 1.25v ( 1 + R56 / R57 ) + R56 *(- Iadj )
  Iadj = 50E-6Amp
- D7 protects againts C40 (input shorts)
  D8 protects againts C42 (output shorts)
  Vout = 1.25v ( 1 + R55 / R54 ) + R55 * Iadj
  Iadj = 50E-6Amp
- ±18v POWER LEDS  REAR PANEL

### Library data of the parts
C28 C30-C32 = CAP_2917_10µF_50v: Manufacturers Part Number: TCJD106M050R0120; Checked: yes
C29 C33 = MYCAP: as C12 on sheet OPAMP_SUM
D7 D8 = DIODE_S1BB: Manufacturers Part Number: S1BB-13-F; Checked: y; Value: S1BB-FDICT-ND
D9 D11 = DIODE RB160M-60TR: Checked: yes; Value: RB160M-60CT-ND
D10 D12 = DIODE_S1BB: Manufacturers Part Number: S1BB-13-F; Checked: yes; Value: S1BB-FDICT-ND
P13 P14 = Header 2p 0.156inch: Manufacturers Part Number: 3-641210-2; Checked: yes; Value: A31688-ND
P15 P16 = Mechanical Part: 2 Position Rectangular Housing Connector Receptacle Natural 0.156" (3.96mm); Manufacturers Part Number: 770849-2; Checked: yes; Value: A24111-ND
P_LED12 P_LED13 = Mechanical Part: Manufacturers Part Number: 5100H5; Checked: yes; Value: Green 2.2v 30mA
P_PIN11 P_PIN14 P_PIN17 P_PIN18 = Mechanical Part: Manufacturers Part Number: 770476-2; Checked: yes
Part8 Part9 = Mechanical Part: Manufacturers Part Number: V8508F; Checked: yes; Value: AE10852-ND
R47 = 1206_Res_249: Manufacturers Part Number: ERA-8AEB2490V
R48 = 1206_Res_2.74K: Manufacturers Part Number: ERA-8AEB2741V; Checked: yes
R49 = 1206_Res_1.33K: Manufacturers Part Number: ERA-8AEB1331V; Checked: yes
R50 = 1206_Res_120R: Manufacturers Part Number: ERA-8AEB121V; Checked: yes
R53 R54 = 1206_Res_10K 1%: as R51 on sheet HeaterDriver
TP15-TP23 = TESTPT: as TP2 on sheet Relay
U11 = LM317: Manufacturers Part Number: LM317T/NOPB; Checked: y; Value: LM317TNS/NOPB-ND
U12 = LDO LM337: Manufacturers Part Number: LM337TNS/NOPB; Checked: y; Value: LM337TNS/NOPB-ND

## Sheet HeaterDriverCircuit.SchDoc: Heater Driver Circuit
size A; Organization: LIGO Laboratory; Address1: California Institute of Technology; Address2: Massachusetts Institute of Technology; DocumentNumber: D1600454; Revision: v2; SheetNumber: 7; SheetTotal: 8; Engineer: L.Sánchez
Used 2 times, as channels HDPRail, HDNRail. Parts and nets are listed once, with the designators drawn on the sheet.
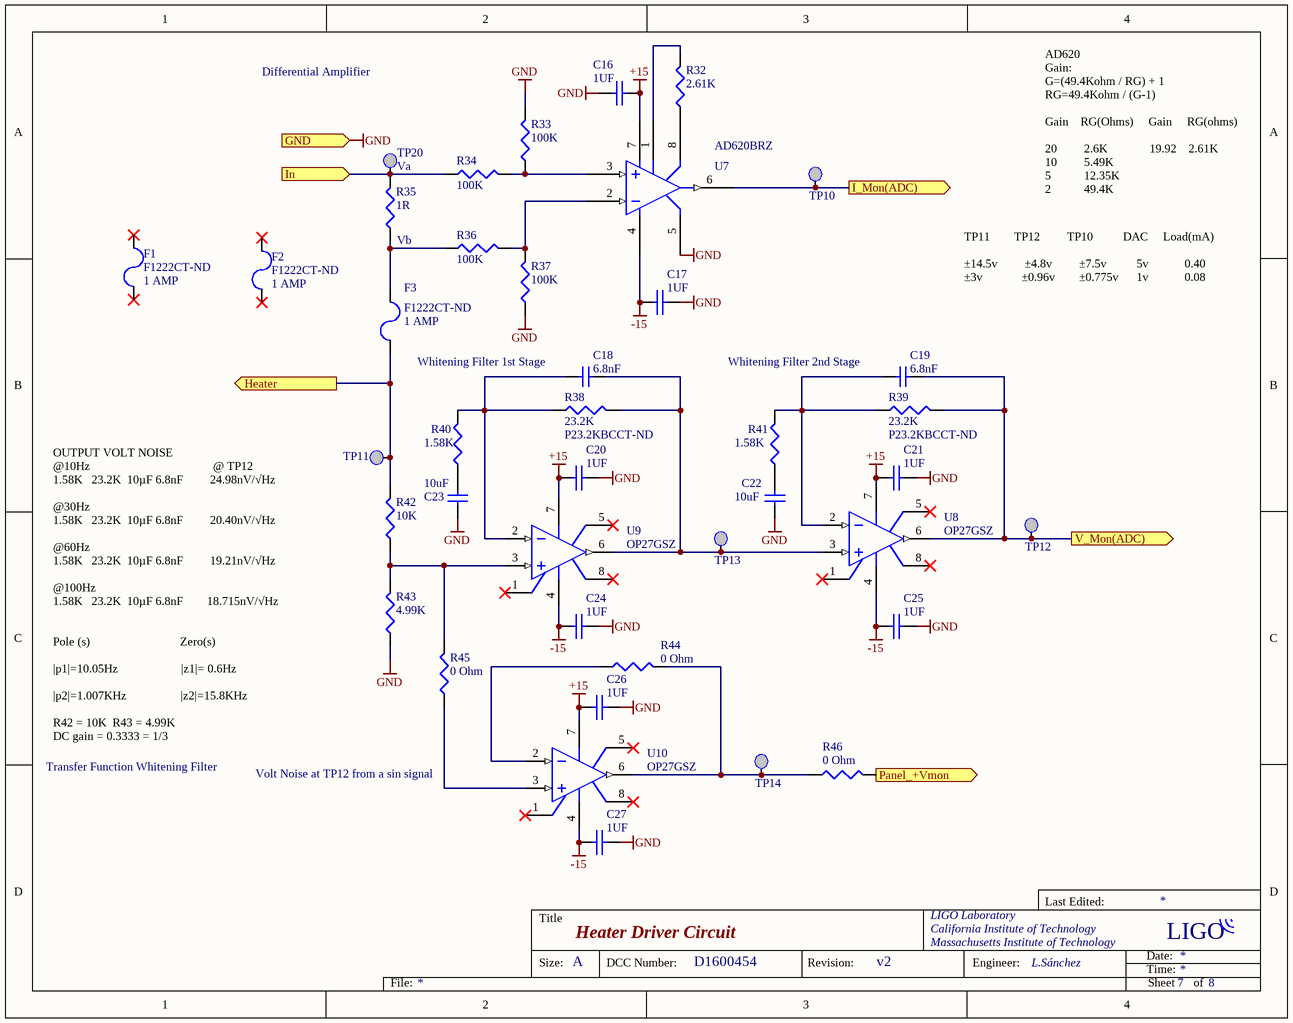
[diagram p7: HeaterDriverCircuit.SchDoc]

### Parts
C16  1UF  [3216[1206]]
C17  1UF  [3216[1206]]
C18  value 6.8nF  [CAP_FILM_POLY_0.197inch]  (hidden comment: Cap Film 6.8nF 100V 5% Polyester 0.197inch)
C19  value 6.8nF  [CAP_FILM_POLY_0.197inch]  (hidden comment: Cap Film 6.8nF 100V 5% Polyester 0.197inch)
C20  1UF  [3216[1206]]
C21  1UF  [3216[1206]]
C22  value 10uF  [CAP_FILM_0.886inch]  (hidden comment: Cap Film 10uF 100v 0.886inch)
C23  value 10uF  [CAP_FILM_0.886inch]  (hidden comment: Cap Film 10uF 100v 0.886inch)
C24  1UF  [3216[1206]]
C25  1UF  [3216[1206]]
C26  1UF  [3216[1206]]
C27  1UF  [3216[1206]]
F1  value 1 AMP  Supplier Part Number 1: F1222CT-ND  [SMD FUSE]  (hidden comment: FUSE BRD MNT 1A 125VAC/VDC 2SMD)
F2  value 1 AMP  Supplier Part Number 1: F1222CT-ND  [SMD FUSE]  (hidden comment: FUSE BRD MNT 1A 125VAC/VDC 2SMD)
F3  value 1 AMP  Supplier Part Number 1: F1222CT-ND  [SMD FUSE]  (hidden comment: FUSE BRD MNT 1A 125VAC/VDC 2SMD)
R32  value 2.61K  [1206]  (hidden comment: RES SMD 2.61K OHM 0.1% 1/4W 1206)
R33  value 100K  [1206]  (hidden comment: SMD Res 1206 100K 0.25W)
R34  value 100K  [1206]  (hidden comment: SMD Res 1206 100K 0.25W)
R35  value 1R  [D2PAK_RES]  (hidden comment: RES SMD 1 OHM 1% 35W D2PAK)
R36  value 100K  [1206]  (hidden comment: SMD Res 1206 100K 0.25W)
R37  value 100K  [1206]  (hidden comment: SMD Res 1206 100K 0.25W)
R38  value 23.2K  Supplier Part Number 1: P23.2KBCCT-ND  [1206]  (hidden comment: SMD Res 1206 23.2K 0.1% 0.25W)
R39  value 23.2K  Supplier Part Number 1: P23.2KBCCT-ND  [1206]  (hidden comment: SMD Res 1206 23.2K 0.1% 0.25W)
R40  value 1.58K  [1206]  (hidden comment: SMD Res 1.58K 0.1% 0.25W 1206)
R41  value 1.58K  [1206]  (hidden comment: SMD Res 1.58K 0.1% 0.25W 1206)
R42  value 10K  [1206]  (hidden comment: 10K Resistor 1206 0.25W 0.1%)
R43  value 4.99K  [1206]  (hidden comment: RES SMD 4.99K OHM 0.1% 1/4W 1206)
R44  0 Ohm  [3216[1206]]
R45  0 Ohm  [3216[1206]]
R46  0 Ohm  [3216[1206]]
TP10  TESTPT  [smt_tp]  (value not drawn)
TP11  TESTPT  [smt_tp]  (value not drawn)
TP12  TESTPT  [smt_tp]  (value not drawn)
TP13  TESTPT  [smt_tp]  (value not drawn)
TP14  TESTPT  [smt_tp]  (value not drawn)
TP20  TESTPT  [smt_tp]  (value not drawn)
U7  AD620BRZ  [SOIC_8P_]
U8  OP27GSZ  [SO8_N]
U9  OP27GSZ  [SO8_N]
U10  OP27GSZ  [SO8_N]

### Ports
GND, Heater (out), I_Mon(ADC) (out), In (in), Panel_+Vmon (out), V_Mon(ADC) (out)

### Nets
+15: C16.2 C20.1 C21.1 C26.1 U7.7(+Vs) U8.7(V+) U9.7(V+) U10.7(V+)
-15: C17.1 C24.1 C25.1 C27.1 U7.4(-Vs) U8.4(V-) U9.4(V-) U10.4(V-)
GND: C16.1 C17.2 C20.2 C21.2 C22.1 C23.1 C24.2 C25.2 C26.2 C27.2 R33.2 R37.1 R43.1 U7.5(REF) ; port GND
Heater: F3.1 R42.2 TP11.1 ; port Heater
I_Mon(ADC): TP10.1 U7.6(OUT) ; port I_Mon(ADC)
In: R34.1 R35.3 TP20.1 ; port In
Panel_+Vmon: R46.2 ; port Panel_+Vmon
V_Mon(ADC): C19.2 R39.2 TP12.1 U8.6(OUT) ; port V_Mon(ADC)
NetC18_1: C18.1 R38.1 R40.2 U9.2(IN-)
NetC18_2: C18.2 R38.2 TP13.1 U8.3(IN+) U9.6(OUT)
NetC19_1: C19.1 R39.1 R41.2 U8.2(IN-)
NetC22_2: C22.2 R41.1
NetC23_2: C23.2 R40.1
NetF3_2: F3.2 R35.1 R36.1
NetR32_1: R32.1 U7.8(RG)
NetR32_2: R32.2 U7.1(RG*)
NetR33_1: R33.1 R34.2 U7.3(+IN)
NetR36_2: R36.2 R37.2 U7.2(-IN)
NetR42_1: R42.1 R43.2 R45.2 U9.3(IN+)
NetR44_1: R44.1 U10.2(IN-)
NetR44_2: R44.2 R46.1 TP14.1 U10.6(OUT)
NetR45_1: R45.1 U10.3(IN+)

Not connected (* = marked no-connect by the designer): F1 1* 2*; F2 1* 2*; U8 1(NULL1)* 5(NC)* 8(NULL2)*; U9 1(NULL1)* 5(NC)* 8(NULL2)*; U10 1(NULL1)* 5(NC)* 8(NULL2)*

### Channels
HDPRail: designators end in _HDPRail; ports GND=GND Heater=NetF3_HDPRail_1 I_Mon(ADC)=NetR27_HDPR_V_DifferentialDriver_1 In=NetP11_1 Panel_+Vmon=NetP7_1 V_Mon(ADC)=NetC19_HDPRail_2
HDNRail: designators end in _HDNRail; ports GND=GND Heater=NetF3_HDNRail_1 I_Mon(ADC)=NetR27_HDNR_I_DifferentialDriver_1 In=NetP11_3 Panel_+Vmon=NetP12_1 V_Mon(ADC)=NetC19_HDNRail_2

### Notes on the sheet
- Differential Amplifier
- (near TP20) Va
- AD620
  Gain:
  G=(49.4Kohm / RG) + 1
  RG=49.4Kohm / (G-1)
  Gain    RG(Ohms)     Gain     RG(ohms)
  20         2.6K              19.92    2.61K
  10         5.49K
  5           12.35K
  2           49.4K
- (near R35) Vb
- TP11        TP12         TP10          DAC     Load(mA)
  ±14.5v         ±4.8v         ±7.5v          5v            0.40
  ±3v             ±0.96v        ±0.775v      1v            0.08
- (near C18) Whitening Filter 1st Stage
- (near C19) Whitening Filter 2nd Stage
- Transfer Function Whitening Filter
- OUTPUT VOLT NOISE
  @10Hz                                         @ TP12
  1.58K   23.2K  10µF 6.8nF         24.98nV/√Hz
  @30Hz
  1.58K   23.2K  10µF 6.8nF         20.40nV/√Hz
  @60Hz
  1.58K   23.2K  10µF 6.8nF         19.21nV/√Hz
  @100Hz
  1.58K   23.2K  10µF 6.8nF        18.715nV/√Hz
  Pole (s)                              Zero(s)
  |p1|=10.05Hz                     |z1|= 0.6Hz
  |p2|=1.007KHz                  |z2|=15.8KHz
  R42 = 10K  R43 = 4.99K
  DC gain = 0.3333 = 1/3
- Volt Noise at TP12 from a sin signal

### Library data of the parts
C16 C17 C20 C21 C24-C27 = MYCAP: as C12 on sheet OPAMP_SUM
C18 C19 = CAP_Radial_6800pF_Polyester: Manufacturers Part Number: QYX2A682JTP; Checked: y
C22 C23 = CAP_10uF_Polyester: Cap Film 10uF 100v +-5% 0.886inch; Manufacturers Part Number: ECQ-E1106JF; Checked: y
F1-F3 = SMD FUSE 1AMP: Manufacturers Part Number: 0154001.DR; Checked: yes
R32 = 1206_Res_5.49K: Manufacturers Part Number: ERA-8AEB2611V; Checked: Yes
R33 R34 R36 R37 = 1206_Res_100K: Manufacturers Part Number: ERA-8AEB104V; Checked: yes
R35 = RES_D2PAK_1R00: 'Manufacturers Part Number: PWR263S-35-1R00F; Checked: Yes
R38 R39 = 1206_Res_23.2K: Manufacturers Part Number: ERA-8AEB2322V; Checked: yes
R40 R41 = 1206_Res_1.58K: Manufacturers Part Number: ERA-8AEB1581V; Checked: yes
R42 = 1206_Res_10K: as R23 on sheet OPAMP_SUM
R43 = 1206_Res_7.5K: Manufacturers Part Number: RT1206BRD074K99L; Checked: yes
R44-R46 = Res3: as R14 on sheet Relay
TP10-TP14 TP20 = TESTPT: as TP2 on sheet Relay
U7 = AD620: Low power instrumentation amplifier; 'Manufacturers Part Number: AD620BRZ-R7; Checked: Yes; Value: AD620BRZ-R7CT-ND
U8-U10 = ADOP27AQ: as U5 on sheet OPAMP_SUM

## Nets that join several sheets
+15: HeaterDriver (R51.2), OPAMP_SUM (C12.1 U5.7), LowPassFilter (C6.1 C7.1 U3.7 U4.7), DR1 (C2_DR1.1 D1_DR1.2 D4_DR1.2 U1_DR1.4), DR2 (C2_DR2.1 D1_DR2.2 D4_DR2.2 U1_DR2.4), DR3 (C2_DR3.1 D1_DR3.2 D4_DR3.2 U1_DR3.4), HDPR_I_DifferentialDriver (C14_HDPR_I_DifferentialDriver.2 U6_HDPR_I_DifferentialDriver.8), HDPR_V_DifferentialDriver (C14_HDPR_V_DifferentialDriver.2 U6_HDPR_V_DifferentialDriver.8), HDNR_I_DifferentialDriver (C14_HDNR_I_DifferentialDriver.2 U6_HDNR_I_DifferentialDriver.8), HDNR_V_DifferentialDriver (C14_HDNR_V_DifferentialDriver.2 U6_HDNR_V_DifferentialDriver.8), Voltage Regulator (7 pins), HDPRail (8 pins), HDNRail (8 pins), DifferentialDriver (C14_DifferentialDriver.2 U6_DifferentialDriver.8)
+18: HeaterDriver (P1.1), Relay (R12.2 R18.1), Voltage Regulator (5 pins)
-15: HeaterDriver (R52.1), OPAMP_SUM (C13.1 U5.4), LowPassFilter (C10.1 C11.1 U3.4 U4.4), DR1 (C3_DR1.1 D1_DR1.1 D4_DR1.1 U1_DR1.13), DR2 (C3_DR2.1 D1_DR2.1 D4_DR2.1 U1_DR2.13), DR3 (C3_DR3.1 D1_DR3.1 D4_DR3.1 U1_DR3.13), HDPR_I_DifferentialDriver (C15_HDPR_I_DifferentialDriver.2 U6_HDPR_I_DifferentialDriver.4), HDPR_V_DifferentialDriver (C15_HDPR_V_DifferentialDriver.2 U6_HDPR_V_DifferentialDriver.4), HDNR_I_DifferentialDriver (C15_HDNR_I_DifferentialDriver.2 U6_HDNR_I_DifferentialDriver.4), HDNR_V_DifferentialDriver (C15_HDNR_V_DifferentialDriver.2 U6_HDNR_V_DifferentialDriver.4), Voltage Regulator (7 pins), HDPRail (8 pins), HDNRail (8 pins), DifferentialDriver (C15_DifferentialDriver.2 U6_DifferentialDriver.4)
-18: HeaterDriver (P1.3), Voltage Regulator (5 pins)
GND: HeaterDriver (13 pins), Relay (R14.1 R15.2 U2.2), OPAMP_SUM (C12.2 C13.2 U5.3), LowPassFilter (6 pins), DR1 (6 pins), DR2 (6 pins), DR3 (6 pins), HDPR_I_DifferentialDriver (C14_HDPR_I_DifferentialDriver.1 C15_HDPR_I_DifferentialDriver.1 U6_HDPR_I_DifferentialDriver.5), HDPR_V_DifferentialDriver (C14_HDPR_V_DifferentialDriver.1 C15_HDPR_V_DifferentialDriver.1 U6_HDPR_V_DifferentialDriver.5), HDNR_I_DifferentialDriver (C14_HDNR_I_DifferentialDriver.1 C15_HDNR_I_DifferentialDriver.1 U6_HDNR_I_DifferentialDriver.5), HDNR_V_DifferentialDriver (C14_HDNR_V_DifferentialDriver.1 C15_HDNR_V_DifferentialDriver.1 U6_HDNR_V_DifferentialDriver.5), Voltage Regulator (17 pins), HDPRail (14 pins), HDNRail (14 pins), DifferentialDriver (C14_DifferentialDriver.1 C15_DifferentialDriver.1 U6_DifferentialDriver.5)
NetC5_1: OPAMP_SUM (R25.1), LowPassFilter (C5.1 TP6.1 U4.2 U4.6)
NetC19_HDNRail_2: HDNR_V_DifferentialDriver (R27_HDNR_V_DifferentialDriver.1 R30_HDNR_V_DifferentialDriver.1 U6_HDNR_V_DifferentialDriver.3), HDNRail (C19_HDNRail.2 R39_HDNRail.2 TP12_HDNRail.1 U8_HDNRail.6)
NetC19_HDPRail_2: HDPR_I_DifferentialDriver (R27_HDPR_I_DifferentialDriver.1 R30_HDPR_I_DifferentialDriver.1 U6_HDPR_I_DifferentialDriver.3), HDPRail (C19_HDPRail.2 R39_HDPRail.2 TP12_HDPRail.1 U8_HDPRail.6)
NetF3_HDNRail_1: HeaterDriver (P8.4), HDNRail (F3_HDNRail.1 R42_HDNRail.2 TP11_HDNRail.1)
NetF3_HDPRail_1: HeaterDriver (P8.1), HDPRail (F3_HDPRail.1 R42_HDPRail.2 TP11_HDPRail.1)
NetH1_1: Relay (H1.1), DR2 (R9_DR2.1 TP1_DR2.1 U1_DR2.10)
NetJ1_1: HeaterDriver (J1.1), DR1 (R2_DR1.2 R4_DR1.2)
NetJ1_2: HeaterDriver (J1.2), DR2 (R2_DR2.2 R4_DR2.2)
NetJ1_3: HeaterDriver (J1.3), DR3 (R2_DR3.2 R4_DR3.2)
NetJ1_6: HeaterDriver (J1.6), DR1 (R7_DR1.2 R10_DR1.1)
NetJ1_7: HeaterDriver (J1.7), DR2 (R7_DR2.2 R10_DR2.1)
NetJ1_8: HeaterDriver (J1.8), DR3 (R7_DR3.2 R10_DR3.1)
NetJ4_1: HeaterDriver (J4.1), HDPR_I_DifferentialDriver (R28_HDPR_I_DifferentialDriver.2)
NetJ4_2: HeaterDriver (J4.2), HDPR_V_DifferentialDriver (R28_HDPR_V_DifferentialDriver.2)
NetJ4_3: HeaterDriver (J4.3), HDNR_V_DifferentialDriver (R28_HDNR_V_DifferentialDriver.2)
NetJ4_4: HeaterDriver (J4.4), HDNR_I_DifferentialDriver (R28_HDNR_I_DifferentialDriver.2)
NetJ4_6: HeaterDriver (J4.6), HDPR_I_DifferentialDriver (R31_HDPR_I_DifferentialDriver.2)
NetJ4_7: HeaterDriver (J4.7), HDPR_V_DifferentialDriver (R31_HDPR_V_DifferentialDriver.2)
NetJ4_8: HeaterDriver (J4.8), HDNR_V_DifferentialDriver (R31_HDNR_V_DifferentialDriver.2)
NetJ4_9: HeaterDriver (J4.9), HDNR_I_DifferentialDriver (R31_HDNR_I_DifferentialDriver.2)
NetP6_1: HeaterDriver (P6.1), DifferentialDriver (R28_DifferentialDriver.2)
NetP6_3: HeaterDriver (P6.3), DifferentialDriver (R31_DifferentialDriver.2)
NetP7_1: HeaterDriver (P7.1), HDPRail (R46_HDPRail.2)
NetP11_1: HeaterDriver (P11.1), HDPRail (R34_HDPRail.1 R35_HDPRail.3 TP20_HDPRail.1)
NetP11_3: HeaterDriver (P11.3), HDNRail (R34_HDNRail.1 R35_HDNRail.3 TP20_HDNRail.1)
NetP12_1: HeaterDriver (P12.1), HDNRail (R46_HDNRail.2)
NetR9_DR1_1: Relay (R13.4 R13.5 TP2.1), DR1 (R9_DR1.1 TP1_DR1.1 U1_DR1.10)
NetR9_DR3_1: LowPassFilter (R19.2), DR3 (R9_DR3.1 TP1_DR3.1 U1_DR3.10)
NetR16_1: Relay (R16.1), OPAMP_SUM (R24.1)
NetR23_2: OPAMP_SUM (R23.2 TP7.1 U5.6), DifferentialDriver (R27_DifferentialDriver.1 R30_DifferentialDriver.1 U6_DifferentialDriver.3)
NetR27_HDNR_I_DifferentialDriver_1: HDNR_I_DifferentialDriver (R27_HDNR_I_DifferentialDriver.1 R30_HDNR_I_DifferentialDriver.1 U6_HDNR_I_DifferentialDriver.3), HDNRail (TP10_HDNRail.1 U7_HDNRail.6)
NetR27_HDPR_V_DifferentialDriver_1: HDPR_V_DifferentialDriver (R27_HDPR_V_DifferentialDriver.1 R30_HDPR_V_DifferentialDriver.1 U6_HDPR_V_DifferentialDriver.3), HDPRail (TP10_HDPRail.1 U7_HDPRail.6)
